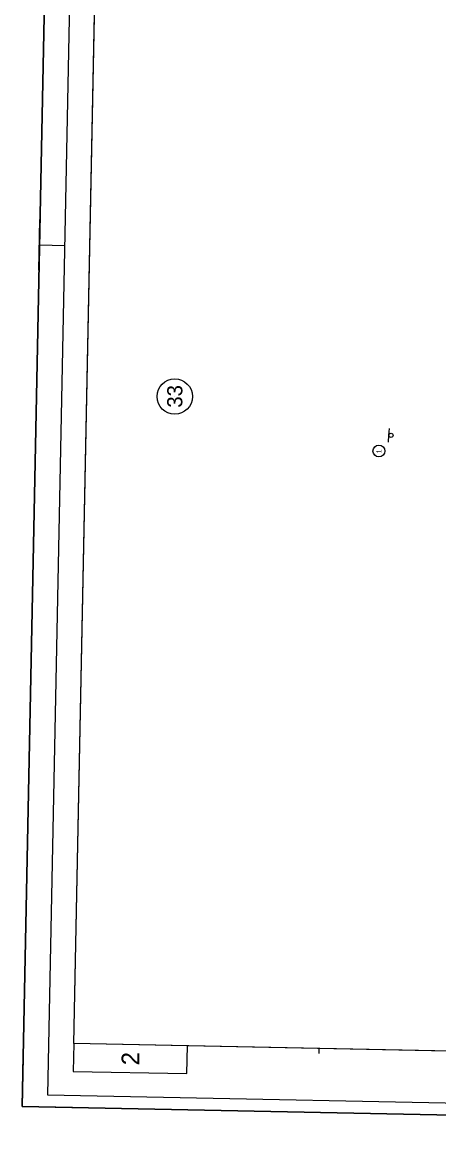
# Model space of a CAD drawing. Extents: x 327762 to 372792, y 127949 to 259367.
# Drawn here: x 344443 to 354757, y 168331 to 195702 of the extents above; entities that cross this region are included whole.
import ezdxf

# ---------------------------------------------------------------- set-up
doc = ezdxf.new("R2010")
doc.units = 0
for name, color, linetype in [('CA-TEXT', 7, 'Continuous'), ('P_MISC_NoPlot', 7, 'Continuous'), ('P_RDWY_Text', 7, 'Continuous'), ('PLT_Sheet_Border', 7, 'Continuous'), ('PLT_Sheet_Info', 7, 'Continuous'), ('SIGNS-POLES', 7, 'Continuous')]:
    doc.layers.add(name, color=color, linetype=linetype)

msp = doc.modelspace()

# ---------------------------------------------------------------- linework, layer by layer
at = {"layer": 'CA-TEXT'}
msp.add_line((348221, 186442), (348221, 186442), dxfattribs=at)
for centre, radius in [((348221, 186442), 437), ((353272, 185095), 147)]:
    msp.add_circle(centre, radius, dxfattribs=at)
at = {"layer": 'P_MISC_NoPlot'}
msp.add_lwpolyline([(345724, 170440), (346294, 198721), (365051, 198328), (365036, 197298), (370642, 197202), (370093, 169949)], close=True, dxfattribs=at)
at = {"layer": 'P_RDWY_Text'}
msp.add_lwpolyline([(344443, 168885), (345298, 211374), (372792, 210820), (371936, 168331)], close=True, dxfattribs=at)
at = {"layer": 'PLT_Sheet_Border'}
for points in [[(371936, 168331), (372792, 210820), (345298, 211374), (344443, 168885)], [(371317, 168643), (372150, 210008), (345907, 210537), (345074, 169172)]]:
    msp.add_lwpolyline(points, close=True, dxfattribs=at)
at = {"layer": 'PLT_Sheet_Info'}
for p, q in [((345724, 170440), (346517, 209806)), ((344859, 189567), (344884, 190817)), ((344872, 190192), (345497, 190179)), ((370718, 169937), (345724, 170440)), ((351785, 170318), (351783, 170193)), ((344443, 168885), (344468, 170134)), ((345692, 168859), (344443, 168885))]:
    msp.add_line(p, q, dxfattribs=at)
msp.add_lwpolyline([(345724, 170440), (345710, 169753), (348522, 169696), (348536, 170384)], close=True, dxfattribs=at)
at = {"layer": 'SIGNS-POLES'}
for p, q in [((353520, 185485), (353531, 185653)), ((353509, 185315), (353519, 185484))]:
    msp.add_line(p, q, dxfattribs=at)
msp.add_circle((353572, 185484), 52.2, dxfattribs=at)

# ---------------------------------------------------------------- texts
at = {"layer": 'CA-TEXT'}
for s, height, rotation, p in [('33', 375, 89.767, (348407, 186167)), ('1', 125, 88.8468, (353334, 185037))]:
    msp.add_text(s, height=height, rotation=rotation, dxfattribs=at).set_placement(p)
at = {"layer": 'PLT_Sheet_Info'}
msp.add_text('2', height=437, rotation=88.8462, dxfattribs=at).set_placement((347339, 169900))

doc.saveas('drawing.dxf')
